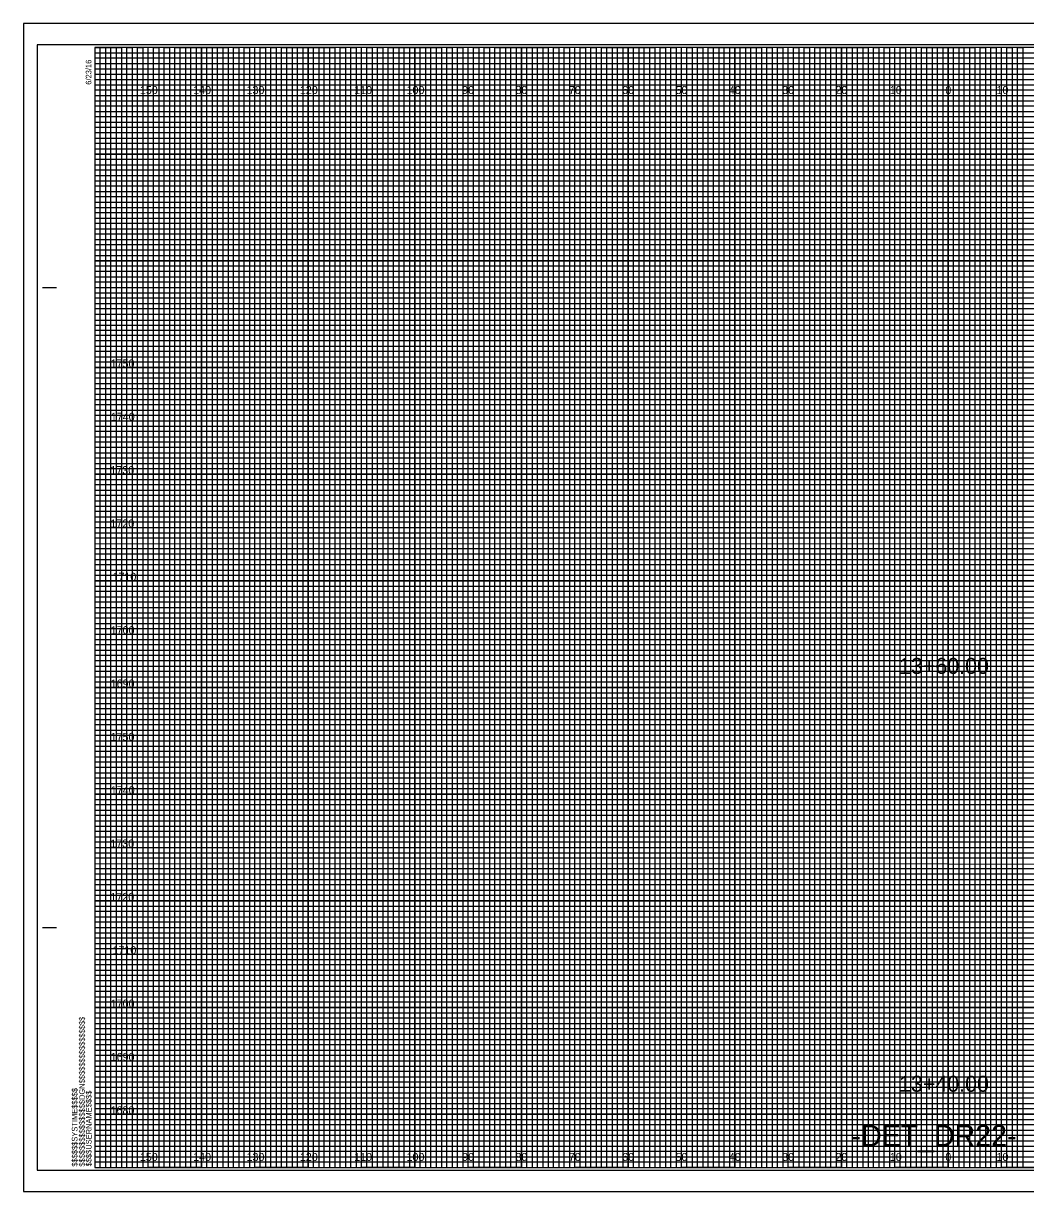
# Model space of a CAD drawing. Extents: x -13 to 323, y -5 to 1314.
# Drawn here: x -13.4 to 174.5, y 875.5 to 1094.5 of the extents above; entities that cross this region are included whole.
import ezdxf

# ---------------------------------------------------------------- set-up
doc = ezdxf.new("R2010")
doc.units = 0
for name, color, linetype in [('Prop Horizontal Alignment', 7, 'Continuous'), ('Prop XS Alignment Label', 7, 'Continuous'), ('Raster_Level_0', 7, 'Continuous'), ('Scratch_Level_3', 7, 'Continuous'), ('Sheet Cross Section CELL', 7, 'Continuous'), ('Sheet Cross Section Grid Major CELL', 7, 'Continuous'), ('Sheet Cross Section Grid Middle CELL', 7, 'Continuous'), ('Sheet Cross Section Grid Minor 1 CELL', 7, 'Continuous'), ('Sheet Cross Section Grid Minor 2 CELL', 7, 'Continuous'), ('Sheet Cutting Line CELL', 7, 'Continuous'), ('Sheet DOT Grid CELL', 7, 'Continuous'), ('Sheet Plot Border Inside CELL', 7, 'Continuous'), ('Sheet Plot Border Outside CELL', 7, 'Continuous')]:
    doc.layers.add(name, color=color, linetype=linetype)

msp = doc.modelspace()

# ---------------------------------------------------------------- linework, layer by layer
at = {"layer": 'Sheet Cross Section CELL'}
for p, q in [((-9.8, 1045), (-7.3, 1045)), ((-9.7, 1045), (-7.2, 1045)), ((-9.8, 925), (-7.3, 925)), ((-9.7, 925), (-7.2, 925)), ((0, 880), (0, 880)), ((0, 880), (0, 880)), ((0, 880), (0, 880)), ((0, 880), (0, 880)), ((0, 880), (0, 880)), ((0, 880), (0, 880)), ((0, 880), (0, 880))]:
    msp.add_line(p, q, dxfattribs=at)
msp.add_lwpolyline([(320, 1090), (0, 1090), (0, 880), (320, 880)], close=True, dxfattribs=at)
at = {"layer": 'Sheet Cross Section Grid Major CELL'}
for p, q in [((10, 1090), (0, 1090)), ((10, 880), (10, 1090)), ((30, 1090), (20, 1090)), ((20, 1090), (20, 880)), ((30, 880), (30, 1090)), ((50, 1090), (40, 1090)), ((40, 1090), (40, 880)), ((50, 880), (50, 1090)), ((70, 1090), (60, 1090)), ((60, 1090), (60, 880)), ((70, 880), (70, 1090)), ((90, 1090), (80, 1090)), ((80, 1090), (80, 880)), ((90, 880), (90, 1090)), ((110, 1090), (100, 1090)), ((100, 1090), (100, 880)), ((110, 880), (110, 1090)), ((130, 1090), (120, 1090)), ((120, 1090), (120, 880)), ((130, 880), (130, 1090)), ((150, 1090), (140, 1090)), ((140, 1090), (140, 880)), ((150, 880), (150, 1090)), ((170, 1090), (160, 1090)), ((160, 1090), (160, 880)), ((170, 880), (170, 1090)), ((20, 880), (10, 880)), ((40, 880), (30, 880)), ((60, 880), (50, 880)), ((80, 880), (70, 880)), ((100, 880), (90, 880)), ((120, 880), (110, 880)), ((140, 880), (130, 880)), ((160, 880), (150, 880)), ((180, 880), (170, 880))]:
    msp.add_line(p, q, dxfattribs=at)
for points in [[(0, 1080), (320, 1080), (320, 1070), (0, 1070)], [(0, 1060), (320, 1060), (320, 1050), (0, 1050)], [(0, 1040), (320, 1040), (320, 1030), (0, 1030)], [(0, 1020), (320, 1020), (320, 1010), (0, 1010)], [(0, 1000), (320, 1000), (320, 990), (0, 990)], [(0, 980), (320, 980), (320, 970), (0, 970)], [(0, 960), (320, 960), (320, 950), (0, 950)], [(0, 940), (320, 940), (320, 930), (0, 930)], [(0, 920), (320, 920), (320, 910), (0, 910)], [(0, 900), (320, 900), (320, 890), (0, 890)]]:
    msp.add_lwpolyline(points, dxfattribs=at)
at = {"layer": 'Sheet Cross Section Grid Middle CELL'}
for points in [[(0, 1090), (5, 1090), (5, 880), (15, 880), (15, 1090), (25, 1090), (25, 880), (35, 880), (35, 1090), (45, 1090), (45, 880), (55, 880), (55, 1090), (65, 1090), (65, 880), (75, 880), (75, 1090), (85, 1090), (85, 880), (95, 880), (95, 1090), (105, 1090), (105, 880), (115, 880), (115, 1090), (125, 1090), (125, 880), (135, 880), (135, 1090), (145, 1090), (145, 880), (155, 880), (155, 1090), (165, 1090), (165, 880), (175, 880)], [(0, 1085), (275, 1085)], [(0, 1065), (320, 1065), (320, 1075), (0, 1075)], [(0, 1045), (320, 1045), (320, 1055), (0, 1055)], [(0, 1025), (320, 1025), (320, 1035), (0, 1035)], [(0, 1005), (320, 1005), (320, 1015), (0, 1015)], [(0, 985), (320, 985), (320, 995), (0, 995)], [(0, 965), (320, 965), (320, 975), (0, 975)], [(0, 945), (320, 945), (320, 955), (0, 955)], [(0, 925), (320, 925), (320, 935), (0, 935)], [(0, 905), (320, 905), (320, 915), (0, 915)], [(0, 885), (320, 885), (320, 895), (0, 895)]]:
    msp.add_lwpolyline(points, dxfattribs=at)
at = {"layer": 'Sheet Cross Section Grid Minor 1 CELL'}
for p, q in [((0, 1089), (260, 1089)), ((260, 1087.98), (0, 1087.98)), ((0, 1087.98), (0, 1087)), ((0, 1087), (260, 1087)), ((260, 1085.89), (0, 1085.89)), ((0, 1085.89), (0, 1084)), ((0, 1084), (320, 1084))]:
    msp.add_line(p, q, dxfattribs=at)
for points in [[(0, 1083), (270, 1083), (320, 1083), (320, 1082), (0, 1082)], [(0, 1081), (320, 1081), (320, 1079), (0, 1079)], [(0, 1078), (320, 1078), (320, 1077), (0, 1076.98)], [(0, 1076), (320, 1076), (320, 1074), (0, 1074)], [(0, 1073), (320, 1073), (320, 1072), (0, 1072)], [(0, 1071), (320, 1071), (320, 1069), (0, 1069)], [(0, 1068), (320, 1068), (320, 1067), (0, 1067)], [(0, 1066), (320, 1066), (320, 1064), (0, 1064)], [(0, 1063), (320, 1063), (320, 1062), (0, 1062)], [(0, 1061), (320, 1061), (320, 1059), (0, 1059)], [(0, 1058), (320, 1058), (320, 1057), (0, 1057)], [(0, 1056), (320, 1056), (320, 1053.95), (320, 1053), (320, 1052), (0, 1052)], [(0, 1054), (320, 1054), (320, 1053), (0, 1053)], [(0, 1051), (320, 1051), (320, 1049), (0, 1049.03)], [(0, 1049.03), (320, 1049), (320, 1048), (0, 1048)], [(0, 1047), (320, 1047), (320, 1046), (0, 1046)], [(0, 1044), (320, 1044), (320, 1043), (0, 1043)], [(0, 1042), (320, 1042), (320, 1041), (0, 1041)], [(-0.07, 1038.89), (320, 1038.89), (320, 1037.88), (-0.07, 1037.88)], [(0, 1037), (320, 1037), (320, 1036), (0, 1036)], [(0, 1034), (320, 1034), (320, 1033), (0, 1033)], [(0, 1032), (320, 1032), (320, 1031), (0, 1031)], [(0, 1029), (320, 1029), (320, 1028), (0, 1028)], [(0, 1027), (320, 1027), (320, 1026), (0, 1026)], [(0, 1024), (320, 1024), (320, 1023), (0, 1023)], [(0, 1022), (320, 1022), (320, 1021), (0, 1021)], [(0, 1019), (320, 1019), (319.99, 1017.98), (0, 1018)], [(0, 1017), (320, 1017), (320, 1016), (0, 1016)], [(0, 1014), (320, 1014), (320, 1013), (0, 1013)], [(0, 1012), (320, 1012), (320, 1011), (0, 1011)], [(0, 1009), (320, 1009), (320, 1008), (0, 1008)], [(0, 1007), (320, 1007), (320, 1006), (0, 1006)], [(0, 1004), (320, 1004), (320, 1003), (0, 1003)], [(0, 1002), (320, 1002), (320, 1001), (0, 1001)], [(0, 999), (320, 999), (320, 998), (0, 998)], [(0, 996.99), (320.07, 996.91), (320, 996), (0, 996)], [(0, 994), (320, 994), (320, 993), (0, 993)], [(0, 992), (320, 992), (320, 991), (0, 991)], [(0, 989), (320, 989), (320, 988), (0, 988)], [(0, 987), (320, 987), (320, 986), (0, 986)], [(0, 984), (320, 984), (320, 983), (0, 983)], [(0, 982), (320, 982), (320, 981), (0, 981)], [(0, 979), (320, 979), (320, 978), (0, 978)], [(0, 977), (320, 977), (320, 976), (0, 976)], [(0, 974), (320, 974), (320, 973), (0, 973)], [(0, 972), (320, 972), (320, 971), (0, 971)], [(0, 969), (320, 969), (320, 968), (0, 968)], [(0, 967), (320, 967), (320, 966), (0, 966)], [(0, 964), (320, 964), (320, 963), (0, 963)], [(0, 962), (320, 962), (320, 961), (0, 961)], [(0, 959), (320, 959), (319.99, 957.98), (0, 958)], [(0, 957), (320, 957), (320, 956), (0, 956)], [(0, 954), (320, 954), (320, 953), (0, 953)], [(0, 952), (320, 952), (320, 951), (0, 951)], [(0, 949), (320, 949), (320, 948), (0, 948)], [(0, 947), (320, 947), (320, 946), (0, 946)], [(0, 944), (320, 944), (320, 943), (0, 943)], [(0, 942), (320, 942), (320, 941), (0, 941)], [(0, 939), (320, 939), (320, 938), (0, 938)], [(0, 936.99), (320.07, 936.91), (320, 936), (0, 936)], [(0, 934), (320, 934), (320, 933), (0, 933)], [(0, 932), (320, 932), (320, 931), (0, 931)], [(0, 929), (320, 929), (320, 928), (0, 928)], [(0, 927), (320, 927), (320, 926), (0, 926)], [(0, 924), (320, 924), (320, 923), (0, 923)], [(0, 922), (320, 922), (320, 921), (0, 921)], [(0, 919), (320, 919), (320, 918), (0, 918)], [(0, 917), (320, 917), (320, 916), (0, 916)], [(0, 914), (320, 914), (320, 913), (0, 913)], [(0, 912), (320, 912), (320, 911), (0, 911)], [(0, 909), (320, 909), (320, 908), (0, 908)], [(0, 907), (320, 907), (320, 906), (0, 906)], [(0, 904), (320, 904), (320, 903), (0, 903)], [(0, 902), (320, 902), (320, 901), (0, 901)], [(0, 899), (320, 899), (320, 898), (0, 898)], [(0, 897), (320, 897), (320, 896), (0, 896)], [(0, 894), (320, 894), (320, 893), (0, 893)], [(0, 892), (320, 892), (320, 891), (0, 891)], [(0, 889), (320, 889), (320, 888), (0, 888)], [(0, 887), (320, 887), (320, 886), (0, 886)], [(0, 884), (320, 884), (320, 883), (0, 883)], [(0, 882), (320, 882), (320, 881), (0, 881)]]:
    msp.add_lwpolyline(points, dxfattribs=at)
at = {"layer": 'Sheet Cross Section Grid Minor 2 CELL'}
for points in [[(0, 880), (1, 880), (1, 1090), (2, 1090), (2, 880)], [(2, 880), (3, 880), (3, 1090), (4, 1090), (4, 880)], [(5, 880), (6, 880), (6, 1090), (7, 1090), (7, 880)], [(7, 880), (8, 880), (8, 1090), (9, 1090), (9, 880)], [(10, 880), (11, 880), (11, 1090), (12, 1090), (12, 880)], [(12, 880), (13, 880), (13, 1090), (14, 1090), (14, 880)], [(15, 880), (16, 880), (16, 1090), (17, 1090), (17, 880)], [(17, 880), (18, 880), (18, 1090), (19, 1090), (19, 880)], [(20, 880), (21, 880), (21, 1090), (22, 1090), (22, 880)], [(22, 880), (23, 880), (23, 1090), (24, 1090), (24, 880)], [(25, 880), (26, 880), (26, 1090), (27, 1090), (27, 880)], [(27, 880), (28, 880), (28, 1090), (29, 1090), (29, 880)], [(30, 880), (31, 880), (31, 1090), (32, 1090), (32, 880)], [(32, 880), (33, 880), (33, 1090), (34, 1090), (34, 880)], [(35, 880), (36, 880), (36, 1090), (37, 1090), (37, 880)], [(37, 880), (38, 880), (38, 1090), (39, 1090), (39, 880)], [(40, 880), (41, 880), (41, 1090), (42, 1090), (42, 880)], [(42, 880), (43, 880), (43, 1090), (44, 1090), (44, 880)], [(45, 880), (46, 880), (46, 1090), (47, 1090), (47, 880)], [(47, 880), (48, 880), (48, 1090), (49, 1090), (49, 880)], [(50, 880), (51, 880), (51, 1090), (52, 1090), (52, 880)], [(52, 880), (53, 880), (53, 1090), (54, 1090), (54, 880)], [(55, 880), (56, 880), (56, 1090), (57, 1090), (57, 880)], [(57, 880), (58, 880), (58, 1090), (59, 1090), (59, 880)], [(60, 880), (61, 880), (61, 1090), (62, 1090), (62, 880)], [(62, 880), (63, 880), (63, 1090), (64, 1090), (64, 880)], [(65, 880), (66, 880), (66, 1090), (67, 1090), (67, 880)], [(67, 880), (68, 880), (68, 1090), (69, 1090), (69, 880)], [(70, 880), (71, 880), (71, 1090), (72, 1090), (72, 880)], [(72, 880), (73, 880), (73, 1090), (74, 1090), (74, 880)], [(75, 880), (76, 880), (76, 1090), (77, 1090), (77, 880)], [(77, 880), (78, 880), (78, 1090), (79, 1090), (79, 880)], [(80, 880), (81, 880), (81, 1090), (82, 1090), (82, 880)], [(82, 880), (83, 880), (83, 1090), (84, 1090), (84, 880)], [(85, 880), (86, 880), (86, 1090), (87, 1090), (87, 880)], [(87, 880), (88, 880), (88, 1090), (89, 1090), (89, 880)], [(90, 880), (91, 880), (91, 1090), (92, 1090), (92, 880)], [(92, 880), (93, 880), (93, 1090), (94, 1090), (94, 880)], [(95, 880), (96, 880), (96, 1090), (97, 1090), (97, 880)], [(97, 880), (98, 880), (98, 1090), (99, 1090), (99, 880)], [(100, 880), (101, 880), (101, 1090), (102, 1090), (102, 880)], [(102, 880), (103, 880), (103, 1090), (104, 1090), (104, 880)], [(105, 880), (106, 880), (106, 1090), (107, 1090), (107, 880)], [(107, 880), (108, 880), (108, 1090), (109, 1090), (109, 880)], [(110, 880), (111, 880), (111, 1090), (112, 1090), (112, 880)], [(112, 880), (113, 880), (113, 1090), (114, 1090), (114, 880)], [(115, 880), (116, 880), (116, 1090), (117, 1090), (117, 880)], [(117, 880), (118, 880), (118, 1090), (119, 1090), (119, 880)], [(120, 880), (121, 880), (121, 1090), (122, 1090), (122, 880)], [(122, 880), (123, 880), (123, 1090), (124, 1090), (124, 880)], [(125, 880), (126, 880), (126, 1090), (127, 1090), (127, 880)], [(127, 880), (128, 880), (128, 1090), (129, 1090), (129, 880)], [(130, 880), (131, 880), (131, 1090), (132, 1090), (132, 880)], [(132, 880), (133, 880), (133, 1090), (134, 1090), (134, 880)], [(135, 880), (136, 880), (136, 1090), (137, 1090), (137, 880)], [(137, 880), (138, 880), (138, 1090), (139, 1090), (139, 880)], [(140, 880), (141, 880), (141, 1090), (142, 1090), (142, 880)], [(142, 880), (143, 880), (143, 1090), (144, 1090), (144, 880)], [(145, 880), (146, 880), (146, 1090), (147, 1090), (147, 880)], [(147, 880), (148, 880), (148, 1090), (149, 1090), (149, 880)], [(150, 880), (151, 880), (151, 1090), (152, 1090), (152, 880)], [(152, 880), (153, 880), (153, 1090), (154, 1090), (154, 880)], [(155, 880), (156, 880), (156, 1090), (157, 1090), (157, 880)], [(157, 880), (158, 880), (158, 1090), (159, 1090), (159, 880)], [(160, 880), (161, 880), (161, 1090), (162, 1090), (162, 880)], [(162, 880), (163, 880), (163, 1090), (164, 1090), (164, 880)], [(165, 880), (166, 880), (166, 1090), (167, 1090), (167, 880)], [(167, 880), (168, 880), (168, 1090), (169, 1090), (169, 880)], [(170, 880), (171, 880), (171, 1090), (172, 1090), (172, 880)], [(172, 880), (173, 880), (173, 1090), (174, 1090), (174, 880)]]:
    msp.add_lwpolyline(points, dxfattribs=at)
at = {"layer": 'Sheet Cutting Line CELL'}
for p, q in [((323.3, 1094.5), (-13.4, 1094.5)), ((-13.4, 1094.5), (-13.4, 875.5)), ((-13.4, 875.5), (323.3, 875.5))]:
    msp.add_line(p, q, dxfattribs=at)
at = {"layer": 'Sheet DOT Grid CELL'}
for p, q in [((10, 880), (10, 1090)), ((20, 880), (20, 1090)), ((30, 880), (30, 1090)), ((40, 880), (40, 1090)), ((50, 880), (50, 1090)), ((60, 880), (60, 1090)), ((70, 880), (70, 1090)), ((80, 880), (80, 1090)), ((90, 880), (90, 1090)), ((100, 880), (100, 1090)), ((110, 880), (110, 1090)), ((120, 880), (120, 1090)), ((130, 880), (130, 1090)), ((140, 880), (140, 1090)), ((150, 880), (150, 1090)), ((160, 880), (160, 1090)), ((170, 880), (170, 1090)), ((0, 1080), (320, 1080)), ((0, 1070), (320, 1070)), ((0, 1060), (320, 1060)), ((0, 1050), (320, 1050)), ((0, 1040), (320, 1040)), ((0, 1030), (320, 1030)), ((0, 1020), (320, 1020)), ((0, 1010), (320, 1010)), ((0, 1000), (320, 1000)), ((0, 990), (320, 990)), ((0, 980), (320, 980)), ((0, 970), (320, 970)), ((0, 960), (320, 960)), ((0, 950), (320, 950)), ((0, 940), (320, 940)), ((0, 930), (320, 930)), ((0, 920), (320, 920)), ((0, 910), (320, 910)), ((0, 900), (320, 900)), ((0, 890), (320, 890))]:
    msp.add_line(p, q, dxfattribs=at)
at = {"layer": 'Sheet Plot Border Inside CELL'}
msp.add_lwpolyline([(-10.8, 879.5), (322.4, 879.5), (322.4, 1090.5), (-10.8, 1090.5)], close=True, dxfattribs=at)
at = {"layer": 'Sheet Plot Border Outside CELL'}
msp.add_lwpolyline([(-13.4, 875.5), (323.3, 875.5), (323.3, 1094.5), (-13.4, 1094.5)], close=True, dxfattribs=at)

# ---------------------------------------------------------------- texts
at = {"layer": 'Prop Horizontal Alignment'}
for s, p in [('13+60.00', (150.77, 972.55)), ('13+40.00', (150.77, 894.22))]:
    msp.add_text(s, height=3, dxfattribs=at).set_placement(p)
at = {"layer": 'Prop XS Alignment Label'}
msp.add_text('-DET_DR22-', height=4, dxfattribs=at).set_placement((141.87, 884))
at = {"layer": 'Raster_Level_0'}
for s, p in [('150', (8.44, 1081.25)), ('140', (18.44, 1081.25)), ('130', (28.44, 1081.25)), ('120', (38.44, 1081.25)), ('110', (48.62, 1081.25)), ('100', (58.44, 1081.25)), ('90', (68.86, 1081.25)), ('80', (78.86, 1081.25)), ('70', (88.86, 1081.25)), ('60', (98.86, 1081.25)), ('50', (108.86, 1081.25)), ('40', (118.86, 1081.25)), ('30', (128.86, 1081.25)), ('20', (138.86, 1081.25)), ('10', (149.04, 1081.25)), ('0', (159.45, 1081.25)), ('0', (159.45, 1081.25)), ('10', (169.04, 1081.25)), ('150', (8.44, 881.25)), ('140', (18.44, 881.25)), ('130', (28.44, 881.25)), ('120', (38.44, 881.25)), ('110', (48.62, 881.25)), ('100', (58.44, 881.25)), ('90', (68.86, 881.25)), ('80', (78.86, 881.25)), ('70', (88.86, 881.25)), ('60', (98.86, 881.25)), ('50', (108.86, 881.25)), ('40', (118.86, 881.25)), ('30', (128.86, 881.25)), ('20', (138.86, 881.25)), ('10', (149.04, 881.25)), ('0', (159.45, 881.25)), ('0', (159.45, 881.25)), ('10', (169.04, 881.25))]:
    msp.add_text(s, height=1.5, dxfattribs=at).set_placement(p)
at = {"layer": 'Scratch_Level_3'}
for s, p in [('1750', (2.96, 1030)), ('1740', (3, 1020)), ('1730', (2.92, 1010)), ('1720', (2.93, 1000)), ('1710', (3.31, 990)), ('1700', (2.98, 980)), ('1690', (2.97, 970)), ('1750', (2.96, 960)), ('1740', (3, 950)), ('1730', (2.92, 940)), ('1720', (2.93, 930)), ('1710', (3.31, 920)), ('1700', (2.98, 910)), ('1690', (2.97, 900)), ('1680', (2.95, 890))]:
    msp.add_text(s, height=1.5, dxfattribs=at).set_placement(p)
at = {"layer": 'Sheet Cross Section CELL'}
for s, p in [('6/23/16', (-0.65, 1083)), ('$$$$$$$$$$$$$$$$DGN$$$$$$$$$$$$$$$$', (-1.88, 880.18)), ('$$$$$$SYSTIME$$$$$', (-3.26, 880.18)), ('$$$$USERNAME$$$$', (-0.62, 880.23))]:
    msp.add_text(s, height=1.05, rotation=90, dxfattribs=at).set_placement(p)

doc.saveas('drawing.dxf')
